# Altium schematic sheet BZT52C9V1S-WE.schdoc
size 127 x 101 mm
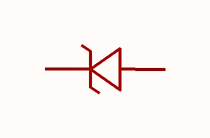
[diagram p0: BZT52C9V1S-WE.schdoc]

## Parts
D?  bzt52c9v1s_c523833  [SOD-323_L1.8-W1.3-LS2.5-RD]  (value not drawn)

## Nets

Not connected (* = marked no-connect by the designer): D? 1(K) 2(A)

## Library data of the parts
D? = bzt52c9v1s_c523833: 二极管配置:1个独立式;稳压值(标称值):9.1V;稳压值(范围值):8.5V~9.6V;耗散功率(Pd):200mW;; Manufacturer: MDD(辰达半导体); AddInBom: yes; SymbolName: BZT52C9V1S-WE; ModelId: db63db13d9e342eb939127d413d6200b; ModelTransform: 104.3305,51.181,0,0,0,0,0,-0.004,0; Diode Configuration: 1个独立式; Zener Voltage(Nom): 9.1V; Reverse Leakage Current (Ir): 500nA@6V; Pd - Power Dissipation: 200mW; Impedance(Zzt): 30Ω; Tolerance: ±5%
